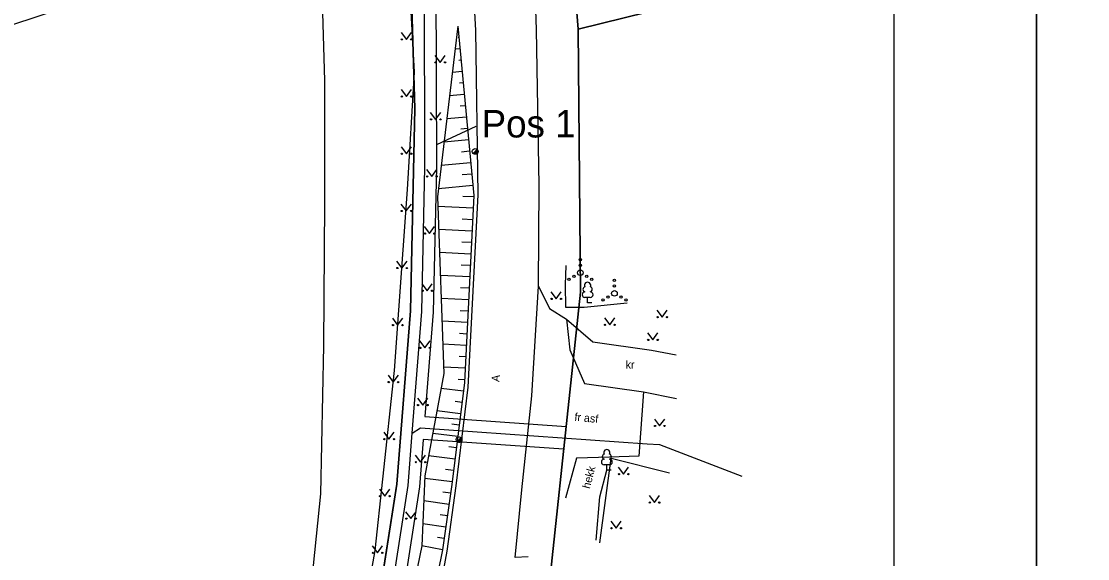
# Model space of a CAD drawing. Extents: x 554947 to 555436, y 6564938 to 6565792.
# Drawn here: x 555146.4 to 555239.7, y 6565248.3 to 6565295.3 of the extents above; entities that cross this region are included whole.
import ezdxf

# ---------------------------------------------------------------- set-up
doc = ezdxf.new("R2010")
doc.units = 0
for name, color, linetype in [('AED', 7, 'Continuous'), ('HALJASTUS', 7, 'Continuous'), ('KASUTUSALA', 7, 'Continuous'), ('KPKAABEL', 7, 'Continuous'), ('PIIR', 7, 'Continuous'), ('POST', 7, 'Continuous'), ('PR_SIDE', 7, 'Continuous'), ('PUU', 7, 'Continuous'), ('RELJEEF', 7, 'Continuous'), ('TEE', 7, 'Continuous'), ('VORMISTUS_1', 7, 'Continuous')]:
    doc.layers.add(name, color=color, linetype=linetype)

msp = doc.modelspace()

# ---------------------------------------------------------------- linework, layer by layer
at = {"layer": 'AED'}
for points in [[(555179.37, 6565300.078), (555180.242, 6565299.846), (555180.75, 6565290.874), (555180.137, 6565280.616), (555178.982, 6565264.788), (555177.984, 6565255.288), (555177.306, 6565249.05), (555173.486, 6565227.422), (555169.733, 6565212.423), (555163.779, 6565189.534), (555156.086, 6565161.758), (555151.428, 6565143.905), (555146.995, 6565125.891), (555142.273, 6565107.514), (555136.767, 6565086.759), (555131.214, 6565064.984), (555128.386, 6565056.617), (555127.142, 6565056.522)], [(555196.969, 6565249.734), (555197.967, 6565257.123), (555203.09, 6565255.853)], [(555196.662, 6565249.943), (555196.993, 6565253.757), (555197.595, 6565256.076)]]:
    msp.add_lwpolyline(points, dxfattribs=at)
at = {"layer": 'HALJASTUS'}
for p, q in [((555179.599, 6565294.336), (555180.062, 6565293.73)), ((555180.062, 6565293.73), (555180.508, 6565294.336)), ((555182.556, 6565292.327), (555183.019, 6565291.721)), ((555183.019, 6565291.721), (555183.465, 6565292.327)), ((555179.599, 6565289.336), (555180.062, 6565288.73)), ((555180.062, 6565288.73), (555180.508, 6565289.336)), ((555182.156, 6565287.343), (555182.62, 6565286.737)), ((555182.62, 6565286.737), (555183.065, 6565287.343)), ((555179.599, 6565284.336), (555180.062, 6565283.73)), ((555180.062, 6565283.73), (555180.508, 6565284.336)), ((555181.818, 6565282.356), (555182.281, 6565281.749)), ((555182.281, 6565281.749), (555182.727, 6565282.356)), ((555179.589, 6565279.337), (555180.053, 6565278.73)), ((555180.053, 6565278.73), (555180.498, 6565279.337)), ((555181.619, 6565277.36), (555182.083, 6565276.753)), ((555182.083, 6565276.753), (555182.528, 6565277.36)), ((555179.211, 6565274.351), (555179.675, 6565273.744)), ((555179.675, 6565273.744), (555180.12, 6565274.351)), ((555181.421, 6565272.364), (555181.884, 6565271.757)), ((555181.884, 6565271.757), (555182.33, 6565272.364)), ((555192.698, 6565271.648), (555193.162, 6565271.041)), ((555193.162, 6565271.041), (555193.607, 6565271.648)), ((555178.833, 6565269.365), (555179.297, 6565268.759)), ((555179.297, 6565268.759), (555179.742, 6565269.365)), ((555197.381, 6565269.385), (555197.844, 6565268.778)), ((555197.844, 6565268.778), (555198.29, 6565269.385)), ((555201.971, 6565270.059), (555202.435, 6565269.452)), ((555202.435, 6565269.452), (555202.88, 6565270.059)), ((555181.222, 6565267.368), (555181.686, 6565266.761)), ((555181.686, 6565266.761), (555182.131, 6565267.368)), ((555201.157, 6565268.064), (555201.62, 6565267.457)), ((555201.62, 6565267.457), (555202.066, 6565268.064)), ((555178.456, 6565264.38), (555178.919, 6565263.773)), ((555178.919, 6565263.773), (555179.365, 6565264.38)), ((555181.024, 6565262.371), (555181.487, 6565261.765)), ((555181.487, 6565261.765), (555181.933, 6565262.371)), ((555201.752, 6565260.544), (555202.215, 6565259.937)), ((555202.215, 6565259.937), (555202.66, 6565260.544)), ((555178.078, 6565259.394), (555178.541, 6565258.787)), ((555178.541, 6565258.787), (555178.987, 6565259.394)), ((555180.825, 6565257.375), (555181.289, 6565256.769)), ((555181.289, 6565256.769), (555181.734, 6565257.375)), ((555198.592, 6565256.328), (555199.055, 6565255.721)), ((555199.055, 6565255.721), (555199.501, 6565256.328)), ((555177.7, 6565254.408), (555178.163, 6565253.802)), ((555178.163, 6565253.802), (555178.609, 6565254.408)), ((555201.288, 6565253.846), (555201.752, 6565253.24)), ((555201.752, 6565253.24), (555202.197, 6565253.846)), ((555179.998, 6565252.444), (555180.462, 6565251.838)), ((555180.462, 6565251.838), (555180.907, 6565252.444)), ((555197.942, 6565251.606), (555198.405, 6565250.999)), ((555198.405, 6565250.999), (555198.851, 6565251.606)), ((555177.065, 6565249.457), (555177.528, 6565248.85)), ((555177.528, 6565248.85), (555177.974, 6565249.457))]:
    msp.add_line(p, q, dxfattribs=at)
msp.add_lwpolyline([(555199.375, 6565270.681), (555195.626, 6565270.307), (555194.015, 6565270.302), (555193.973, 6565272.287), (555194.036, 6565273.964)], dxfattribs=at)
for centre, radius in [((555179.661, 6565293.73), 0.055), ((555180.49, 6565293.73), 0.055), ((555182.618, 6565291.721), 0.055), ((555183.447, 6565291.721), 0.055), ((555179.661, 6565288.73), 0.055), ((555180.49, 6565288.73), 0.055), ((555182.219, 6565286.737), 0.055), ((555183.047, 6565286.737), 0.055), ((555179.661, 6565283.73), 0.055), ((555180.49, 6565283.73), 0.055), ((555181.88, 6565281.749), 0.055), ((555182.709, 6565281.749), 0.055), ((555179.652, 6565278.73), 0.055), ((555180.48, 6565278.73), 0.055), ((555181.682, 6565276.753), 0.055), ((555182.51, 6565276.753), 0.055), ((555195.276, 6565274.485), 0.1), ((555195.276, 6565273.985), 0.1), ((555179.274, 6565273.744), 0.055), ((555180.102, 6565273.744), 0.055), ((555194.711, 6565273.01), 0.1), ((555195.276, 6565273.335), 0.25), ((555195.841, 6565273.01), 0.1), ((555194.276, 6565272.76), 0.1), ((555196.276, 6565272.76), 0.1), ((555198.261, 6565272.678), 0.1), ((555198.261, 6565272.178), 0.1), ((555181.483, 6565271.757), 0.055), ((555182.312, 6565271.757), 0.055), ((555192.761, 6565271.041), 0.055), ((555193.589, 6565271.041), 0.055), ((555197.261, 6565270.953), 0.1), ((555197.696, 6565271.203), 0.1), ((555198.261, 6565271.528), 0.25), ((555198.826, 6565271.203), 0.1), ((555199.261, 6565270.953), 0.1), ((555202.033, 6565269.452), 0.055), ((555202.862, 6565269.452), 0.055), ((555178.896, 6565268.759), 0.055), ((555179.725, 6565268.759), 0.055), ((555197.443, 6565268.778), 0.055), ((555198.272, 6565268.778), 0.055), ((555201.219, 6565267.457), 0.055), ((555202.048, 6565267.457), 0.055), ((555181.285, 6565266.761), 0.055), ((555182.114, 6565266.761), 0.055), ((555178.518, 6565263.773), 0.055), ((555179.347, 6565263.773), 0.055), ((555181.086, 6565261.765), 0.055), ((555181.915, 6565261.765), 0.055), ((555201.814, 6565259.937), 0.055), ((555202.643, 6565259.937), 0.055), ((555178.14, 6565258.787), 0.055), ((555178.969, 6565258.787), 0.055), ((555180.888, 6565256.769), 0.055), ((555181.717, 6565256.769), 0.055), ((555198.654, 6565255.721), 0.055), ((555199.483, 6565255.721), 0.055), ((555177.762, 6565253.802), 0.055), ((555178.591, 6565253.802), 0.055), ((555201.351, 6565253.24), 0.055), ((555202.18, 6565253.24), 0.055), ((555180.061, 6565251.838), 0.055), ((555180.89, 6565251.838), 0.055), ((555198.004, 6565250.999), 0.055), ((555198.833, 6565250.999), 0.055), ((555177.127, 6565248.85), 0.055), ((555177.956, 6565248.85), 0.055)]:
    msp.add_circle(centre, radius, dxfattribs=at)
at = {"layer": 'KASUTUSALA'}
for points in [[(555176.937, 6565240.135), (555179.22, 6565254.85), (555179.244, 6565255.16), (555179.541, 6565258.936), (555179.592, 6565259.587), (555180.41, 6565269.99), (555180.41, 6565269.99), (555180.41, 6565269.99), (555180.588, 6565278.069), (555180.8, 6565287.7), (555180.26, 6565306.43), (555178.11, 6565321.18), (555176.49, 6565331.05), (555172.72, 6565345.23), (555167.67, 6565357.913), (555166.64, 6565360.5), (555160.07, 6565375.54), (555144.16, 6565410.6), (555124.27, 6565454.45)], [(555126.773, 6565453.774), (555135.197, 6565435.201), (555141.868, 6565420.974), (555147.21, 6565409.597), (555154.633, 6565393.273), (555162.36, 6565375.334), (555168.957, 6565360.089), (555174.329, 6565346.596), (555178.447, 6565331.473), (555179.928, 6565322.45), (555181.326, 6565312.983), (555182.005, 6565309.084), (555182.652, 6565298.625), (555182.687, 6565282.55), (555182.408, 6565269.89), (555181.69, 6565260.757), (555194.028, 6565259.888), (555193.816, 6565257.898), (555181.571, 6565258.76), (555181.532, 6565258.735), (555181.208, 6565254.618), (555178.897, 6565239.723)]]:
    msp.add_lwpolyline(points, dxfattribs=at)
at = {"layer": 'KPKAABEL'}
msp.add_lwpolyline([(555126.894, 6565446.731), (555132.737, 6565435.388), (555136.366, 6565427.872), (555142.195, 6565415.637), (555145.001, 6565409.613), (555146.957, 6565405.365), (555152.799, 6565392.474), (555157.576, 6565380.671), (555161.529, 6565371.444), (555166.139, 6565359.889), (555169.783, 6565348.422), (555171.572, 6565337.25), (555172.523, 6565325.522), (555172.476, 6565313.268), (555172.511, 6565302.969), (555172.901, 6565290.135), (555172.887, 6565279.431), (555172.817, 6565266.938), (555172.536, 6565254.014), (555171.281, 6565241.464)], dxfattribs=at)
at = {"layer": 'PIIR'}
for points in [[(555393.069, 6565560.972), (555353.12, 6565523.87), (555343.14, 6565512.46), (555302.6, 6565539.71), (555242.37, 6565583.94), (555179.42, 6565586.32), (555138.98, 6565580.6), (555121.18, 6565602.26), (555116.17, 6565610.5), (555109.96, 6565624.83), (555093.56, 6565628.47), (555079.04, 6565618.4), (555074.13, 6565607.82), (555075.34, 6565593.24), (555091.74, 6565551.94), (555171.91, 6565394.64), (555191.35, 6565341.19), (555195.08, 6565294.61), (555195.28, 6565271.63), (555191.64, 6565237.48)], [(555153.01, 6565448.47), (555207.22, 6565406.57), (555216.83, 6565392.35), (555221.23, 6565376.06), (555206.9, 6565339.44), (555200.72, 6565310.3), (555205.15, 6565297.11), (555195.08, 6565294.61), (555191.35, 6565341.19), (555171.91, 6565394.64), (555091.74, 6565551.94)], [(555176.93, 6565240.09), (555179.22, 6565254.85), (555180.41, 6565269.99), (555180.8, 6565287.7), (555180.26, 6565306.43), (555178.11, 6565321.18), (555176.49, 6565331.05), (555172.72, 6565345.23), (555166.64, 6565360.5), (555160.07, 6565375.54), (555144.16, 6565410.6), (555124.27, 6565454.45)], [(555191.64, 6565237.48), (555195.28, 6565271.63), (555195.08, 6565294.61), (555205.15, 6565297.11), (555275.38, 6565300.17), (555292.52, 6565297.57), (555293.54, 6565286.23), (555256.63, 6565245.54)]]:
    msp.add_lwpolyline(points, dxfattribs=at)
msp.add_lwpolyline([(554962.55, 6565234.93), (555180.26, 6565306.43), (555180.8, 6565287.7), (555180.41, 6565269.99), (555179.22, 6565254.85), (555176.93, 6565240.09), (555172.7, 6565220.76), (555117.14, 6565008.97), (555108.27, 6564991.27)], close=True, dxfattribs=at)
at = {"layer": 'POST'}
for p, q in [((555185.903, 6565283.76), (555186.257, 6565284.113)), ((555184.495, 6565258.565), (555184.848, 6565258.919))]:
    msp.add_line(p, q, dxfattribs=at)
for centre in [(555186.08, 6565283.936), (555184.672, 6565258.742)]:
    msp.add_circle(centre, 0.25, dxfattribs=at)
for centre, radius, start, end in [((555186.08, 6565283.936), 0.225, 224.85406, 45.03563), ((555186.08, 6565283.936), 0.2, 224.84272, 45.04698), ((555186.08, 6565283.936), 0.175, 224.82813, 45.06157), ((555186.08, 6565283.936), 0.15, 224.80867, 45.08103), ((555186.08, 6565283.936), 0.125, 224.78144, 45.10826), ((555186.08, 6565283.936), 0.1, 224.74058, 45.14911), ((555186.08, 6565283.936), 0.075, 224.67249, 45.2172), ((555186.08, 6565283.936), 0.05, 224.53632, 45.35338), ((555186.08, 6565283.936), 0.025, 224.12776, 45.76193), ((555184.672, 6565258.742), 0.225, 224.85406, 45.03563), ((555184.672, 6565258.742), 0.2, 224.84272, 45.04698), ((555184.672, 6565258.742), 0.175, 224.82813, 45.06157), ((555184.672, 6565258.742), 0.15, 224.80867, 45.08103), ((555184.672, 6565258.742), 0.125, 224.78144, 45.10826), ((555184.672, 6565258.742), 0.1, 224.74058, 45.14911), ((555184.672, 6565258.742), 0.075, 224.67249, 45.2172), ((555184.672, 6565258.742), 0.05, 224.53632, 45.35338), ((555184.672, 6565258.742), 0.025, 224.12776, 45.76193)]:
    msp.add_arc(centre, radius, start, end, dxfattribs=at)
at = {"layer": 'PR_SIDE'}
for points in [[(555177.913, 6565239.906), (555180.214, 6565254.734), (555180.573, 6565259.307), (555181.409, 6565269.94), (555181.687, 6565282.56), (555181.652, 6565298.593), (555181.01, 6565308.967), (555180.338, 6565312.825), (555178.94, 6565322.296), (555177.469, 6565331.26), (555173.379, 6565346.279), (555168.033, 6565359.705), (555161.441, 6565374.938), (555153.718, 6565392.868), (555146.302, 6565409.177), (555140.964, 6565420.546), (555137.898, 6565426.982), (555134.288, 6565434.784), (555125.868, 6565453.349)], [(555180.573, 6565259.307), (555181.308, 6565259.781), (555201.118, 6565258.387), (555202.213, 6565258.31), (555209.414, 6565255.559)]]:
    msp.add_lwpolyline(points, dxfattribs=at)
at = {"layer": 'PUU'}
for p, q in [((555196.151, 6565271.175), (555195.671, 6565271.175)), ((555195.911, 6565270.7), (555195.911, 6565271.175)), ((555196.291, 6565270.7), (555195.911, 6565270.7)), ((555197.835, 6565256.551), (555197.355, 6565256.551)), ((555197.595, 6565256.076), (555197.595, 6565256.551)), ((555197.975, 6565256.076), (555197.595, 6565256.076))]:
    msp.add_line(p, q, dxfattribs=at)
for centre, radius, start, end in [((555195.741, 6565271.872), 0.233, 109.02174, 253.14154), ((555195.911, 6565272.22), 0.277, 332.5799, 207.4201), ((555196.081, 6565271.872), 0.233, 286.85082, 70.98591), ((555195.673, 6565271.412), 0.238, 90.0016, 269.3953), ((555196.148, 6565271.412), 0.238, 270.6047, 89.9984), ((555197.425, 6565257.249), 0.233, 109.02174, 253.14154), ((555197.595, 6565257.596), 0.277, 332.5799, 207.4201), ((555197.765, 6565257.249), 0.233, 286.85082, 70.98591), ((555197.358, 6565256.789), 0.238, 90.0016, 269.3953), ((555197.833, 6565256.789), 0.238, 270.6047, 89.9984)]:
    msp.add_arc(centre, radius, start, end, dxfattribs=at)
at = {"layer": 'RELJEEF'}
for p, q in [((555184.659, 6565293.9), (555184.594, 6565293.894)), ((555184.752, 6565292.904), (555184.323, 6565292.864)), ((555184.845, 6565291.908), (555184.652, 6565291.89)), ((555184.938, 6565290.913), (555184.081, 6565290.833)), ((555185.031, 6565289.917), (555184.71, 6565289.887)), ((555185.125, 6565288.922), (555183.838, 6565288.801)), ((555185.218, 6565287.926), (555184.768, 6565287.884)), ((555185.311, 6565286.93), (555183.596, 6565286.77)), ((555185.404, 6565285.935), (555184.825, 6565285.88)), ((555185.497, 6565284.939), (555183.353, 6565284.738)), ((555185.591, 6565283.943), (555184.883, 6565283.877)), ((555185.684, 6565282.948), (555183.111, 6565282.707)), ((555185.777, 6565281.952), (555184.941, 6565281.874)), ((555185.87, 6565280.956), (555182.868, 6565280.675)), ((555185.947, 6565279.96), (555185.004, 6565280.007)), ((555185.898, 6565278.962), (555182.815, 6565279.114)), ((555185.848, 6565277.963), (555184.949, 6565278.007)), ((555185.799, 6565276.964), (555182.888, 6565277.108)), ((555185.749, 6565275.965), (555184.902, 6565276.007)), ((555185.699, 6565274.966), (555182.961, 6565275.102)), ((555185.65, 6565273.968), (555184.854, 6565274.007)), ((555185.6, 6565272.969), (555183.034, 6565273.096)), ((555185.551, 6565271.97), (555184.807, 6565272.007)), ((555185.501, 6565270.971), (555183.108, 6565271.09)), ((555185.452, 6565269.973), (555184.759, 6565270.007)), ((555185.402, 6565268.974), (555183.181, 6565269.084)), ((555185.353, 6565267.975), (555184.712, 6565268.007)), ((555185.303, 6565266.976), (555183.254, 6565267.078)), ((555185.254, 6565265.978), (555184.665, 6565266.007)), ((555185.204, 6565264.979), (555183.327, 6565265.072)), ((555185.154, 6565263.98), (555184.587, 6565264.008)), ((555185.049, 6565262.986), (555183.105, 6565263.225)), ((555184.928, 6565261.993), (555184.326, 6565262.067)), ((555184.806, 6565261.001), (555182.738, 6565261.255)), ((555184.684, 6565260.008), (555184.045, 6565260.087)), ((555184.562, 6565259.016), (555182.371, 6565259.285)), ((555184.44, 6565258.023), (555183.764, 6565258.106)), ((555184.318, 6565257.031), (555182.004, 6565257.315)), ((555184.196, 6565256.038), (555183.484, 6565256.126)), ((555184.074, 6565255.046), (555181.669, 6565255.341)), ((555183.794, 6565253.065), (555181.583, 6565253.383)), ((555183.937, 6565254.055), (555183.244, 6565254.155)), ((555183.652, 6565252.076), (555183.018, 6565252.167)), ((555183.51, 6565251.086), (555181.495, 6565251.375)), ((555183.367, 6565250.096), (555182.792, 6565250.179)), ((555183.225, 6565249.106), (555181.412, 6565249.474))]:
    msp.add_line(p, q, dxfattribs=at)
for points in [[(555184.566, 6565294.895), (555185.953, 6565280.072), (555185.143, 6565263.746), (555184.046, 6565254.819), (555183.226, 6565249.112), (555179.005, 6565228.311), (555174.467, 6565210.622), (555168.444, 6565187.982), (555160.102, 6565161.063), (555157.57, 6565157.837)], [(555184.566, 6565294.895), (555182.784, 6565279.965), (555183.347, 6565264.524), (555181.678, 6565255.565), (555181.412, 6565249.474), (555177.118, 6565228.691), (555172.906, 6565211.208), (555166.985, 6565188.606), (555158.553, 6565161.251), (555157.57, 6565157.837)]]:
    msp.add_lwpolyline(points, dxfattribs=at)
at = {"layer": 'TEE'}
for points in [[(555190.709, 6565248.513), (555189.563, 6565248.443), (555190.146, 6565254.361), (555191.039, 6565262.566), (555191.617, 6565272.16), (555191.671, 6565280.957), (555191.452, 6565294.595), (555190.904, 6565310.102), (555189.89, 6565321.445), (555187.257, 6565336.603), (555183.958, 6565348.1), (555179.78, 6565359.387), (555170.643, 6565380.205), (555162.823, 6565397.349), (555156.491, 6565411.721), (555150.933, 6565424.006), (555146.697, 6565433.416), (555136.695, 6565455.531)], [(555131.266, 6565453.894), (555141.635, 6565431.431), (555145.957, 6565421.634), (555151.76, 6565408.809), (555158.151, 6565395.066), (555165.93, 6565378.047), (555174.733, 6565357.312), (555178.536, 6565346.409), (555181.58, 6565335.07), (555184.177, 6565320.727), (555185.301, 6565309.018), (555186.111, 6565294.522), (555186.299, 6565280.132), (555185.431, 6565263.333), (555184.399, 6565254.7), (555183.594, 6565248.995), (555179.697, 6565227.862)], [(555191.617, 6565272.16), (555192.579, 6565270.195), (555194.074, 6565269.287), (555194.347, 6565266.594), (555195.639, 6565263.65), (555200.815, 6565262.91), (555200.393, 6565257.288), (555197.815, 6565257.202), (555194.937, 6565257.11), (555193.983, 6565253.619)], [(555194.074, 6565269.287), (555196.367, 6565267.28), (555201.508, 6565266.552), (555203.658, 6565266.143)], [(555200.815, 6565262.91), (555203.678, 6565262.346)]]:
    msp.add_lwpolyline(points, dxfattribs=at)
at = {"layer": 'VORMISTUS_1'}
msp.add_line((555182.728, 6565284.528), (555186.158, 6565286.137), dxfattribs=at)
for points in [[(555045.188, 6565158.913), (555235.188, 6565158.913), (555235.188, 6565433.913), (555045.188, 6565433.913)], [(555045.188, 6565433.913), (555235.188, 6565433.913), (555235.188, 6565158.913), (555045.188, 6565158.913)], [(555222.688, 6565184.913), (555057.688, 6565184.913), (555057.688, 6565394.913), (555222.688, 6565394.913)]]:
    msp.add_lwpolyline(points, close=True, dxfattribs=at)

# ---------------------------------------------------------------- texts
at = {"layer": 'HALJASTUS'}
msp.add_text('hekk', height=0.7, rotation=75.37115, dxfattribs=at).set_placement((555196.108, 6565254.407))
at = {"layer": 'TEE'}
for s, rotation, p in [('kr', 359.95437, (555199.239, 6565264.948)), ('A', 84.13165, (555188.192, 6565263.759)), ('fr asf', 354.68871, (555194.739, 6565260.393))]:
    msp.add_text(s, height=0.7, rotation=rotation, dxfattribs=at).set_placement(p)
at = {"layer": 'VORMISTUS_1'}
msp.add_text('Pos 1', height=2.4, dxfattribs=at).set_placement((555186.646, 6565285.154))

doc.saveas('drawing.dxf')
